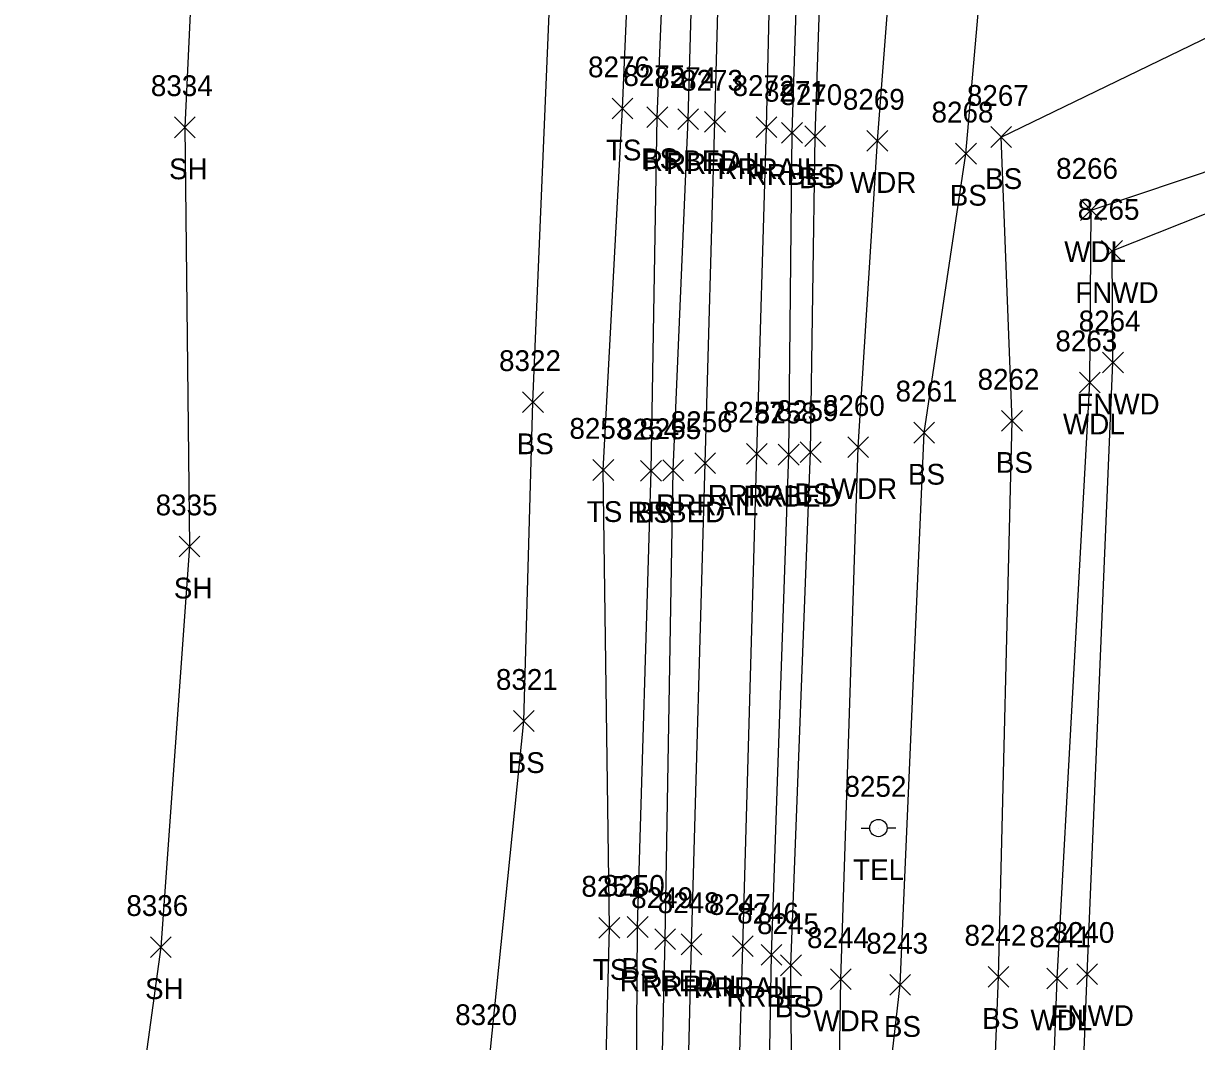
# Model space of a CAD drawing. Extents: x 1769141 to 1770911, y 735471 to 741449.
# Drawn here: x 1770212 to 1770324.8, y 737042.8 to 737140.8 of the extents above; entities that cross this region are included whole.
import ezdxf

# ---------------------------------------------------------------- set-up
doc = ezdxf.new("R2010")
doc.units = 0
for name, color, linetype in [('L_A', 7, 'Continuous'), ('L_I', 7, 'Continuous'), ('L_TIC', 7, 'Continuous'), ('LAWA', 7, 'Continuous'), ('LELB', 7, 'Continuous'), ('LFNC', 7, 'Continuous'), ('LSOGP', 7, 'Continuous'), ('R_A', 7, 'Continuous'), ('R_I', 7, 'Continuous'), ('R_TIC', 7, 'Continuous'), ('RR', 7, 'Continuous'), ('RRB', 7, 'Continuous'), ('U_A', 7, 'Continuous'), ('U_I', 7, 'Continuous'), ('UP', 7, 'Continuous')]:
    doc.layers.add(name, color=color, linetype=linetype)

msp = doc.modelspace()

# ---------------------------------------------------------------- linework, layer by layer
at = {"layer": 'L_TIC'}
for points in [[(1770268.57, 737131.6), (1770270.57, 737133.6)], [(1770270.57, 737131.6), (1770268.57, 737133.6)], [(1770271.92, 737130.76), (1770273.92, 737132.76)], [(1770273.92, 737130.76), (1770271.92, 737132.76)], [(1770226.47, 737129.79), (1770228.47, 737131.79)], [(1770228.47, 737129.79), (1770226.47, 737131.79)], [(1770287.1, 737128.93), (1770289.1, 737130.93)], [(1770289.1, 737128.93), (1770287.1, 737130.93)], [(1770293.09, 737128.48), (1770295.09, 737130.48)], [(1770295.09, 737128.48), (1770293.09, 737130.48)], [(1770305, 737128.85), (1770307, 737130.85)], [(1770307, 737128.85), (1770305, 737130.85)], [(1770301.61, 737127.25), (1770303.61, 737129.25)], [(1770303.61, 737127.25), (1770301.61, 737129.25)], [(1770313.64, 737121.83), (1770315.64, 737123.83)], [(1770315.64, 737121.83), (1770313.64, 737123.83)], [(1770315.66, 737117.89), (1770317.66, 737119.89)], [(1770317.66, 737117.89), (1770315.66, 737119.89)], [(1770315.75, 737107.16), (1770317.75, 737109.16)], [(1770317.75, 737107.16), (1770315.75, 737109.16)], [(1770313.52, 737105.24), (1770315.52, 737107.24)], [(1770315.52, 737105.24), (1770313.52, 737107.24)], [(1770259.96, 737103.34), (1770261.96, 737105.34)], [(1770261.96, 737103.34), (1770259.96, 737105.34)], [(1770306.04, 737101.55), (1770308.04, 737103.55)], [(1770308.04, 737101.55), (1770306.04, 737103.55)], [(1770297.58, 737100.41), (1770299.58, 737102.41)], [(1770299.58, 737100.41), (1770297.58, 737102.41)], [(1770286.67, 737098.53), (1770288.67, 737100.53)], [(1770288.67, 737098.53), (1770286.67, 737100.53)], [(1770291.25, 737099.02), (1770293.25, 737101.02)], [(1770293.25, 737099.02), (1770291.25, 737101.02)], [(1770266.73, 737096.82), (1770268.73, 737098.82)], [(1770268.73, 737096.82), (1770266.73, 737098.82)], [(1770271.32, 737096.75), (1770273.32, 737098.75)], [(1770273.32, 737096.75), (1770271.32, 737098.75)], [(1770226.93, 737089.46), (1770228.93, 737091.46)], [(1770228.93, 737089.46), (1770226.93, 737091.46)], [(1770259.09, 737072.67), (1770261.09, 737074.67)], [(1770261.09, 737072.67), (1770259.09, 737074.67)], [(1770267.31, 737052.77), (1770269.31, 737054.77)], [(1770269.31, 737052.77), (1770267.31, 737054.77)], [(1770270.03, 737052.86), (1770272.03, 737054.86)], [(1770272.03, 737052.86), (1770270.03, 737054.86)], [(1770224.16, 737050.92), (1770226.16, 737052.92)], [(1770226.16, 737050.92), (1770224.16, 737052.92)], [(1770284.78, 737049.17), (1770286.78, 737051.17)], [(1770286.78, 737049.17), (1770284.78, 737051.17)], [(1770289.58, 737047.83), (1770291.58, 737049.83)], [(1770291.58, 737047.83), (1770289.58, 737049.83)], [(1770304.73, 737048.06), (1770306.73, 737050.06)], [(1770306.73, 737048.06), (1770304.73, 737050.06)], [(1770310.39, 737047.91), (1770312.39, 737049.91)], [(1770312.39, 737047.91), (1770310.39, 737049.91)], [(1770313.27, 737048.33), (1770315.27, 737050.33)], [(1770315.27, 737048.33), (1770313.27, 737050.33)], [(1770295.28, 737047.29), (1770297.28, 737049.29)], [(1770297.28, 737047.29), (1770295.28, 737049.29)]]:
    msp.add_lwpolyline(points, dxfattribs=at)
at = {"layer": 'LAWA'}
for points in [[(1770295.56, 736765.07), (1770288.47, 736765.03), (1770285.4, 736787.87), (1770284.57, 736804.63), (1770282.38, 736833.87), (1770287.4, 736893.59), (1770286.58, 736936.63), (1770289.46, 736968.99), (1770291.49, 736986.73), (1770290, 737012.94), (1770290.58, 737048.83), (1770292.25, 737100.02), (1770294.09, 737129.48), (1770297.9, 737178.74), (1770298.45, 737224.98), (1770303.27, 737281.64), (1770303.62, 737324.77), (1770304.03, 737377.4)], [(1770295.56, 736765.07), (1770298.44, 736807.53), (1770300.94, 736833.02), (1770303.15, 736868.46), (1770304.73, 736899.95), (1770312.24, 736920.03), (1770307.96, 736948.77), (1770308.9, 736965.25), (1770306.38, 736996.36), (1770309.8, 737006.68), (1770311.39, 737048.91), (1770314.52, 737106.24), (1770314.64, 737122.83), (1770358.1, 737137.42)]]:
    msp.add_lwpolyline(points, dxfattribs=at)
at = {"layer": 'LELB'}
for points in [[(1770284.22, 736983.53), (1770286.1, 737006.52), (1770285.78, 737050.17), (1770287.67, 737099.53), (1770288.1, 737129.93), (1770289.78, 737179.54), (1770290.91, 737225.58), (1770293.69, 737274.35), (1770294.72, 737325.7), (1770295.85, 737386.33), (1770296.79, 737425.26), (1770298.1, 737467.61), (1770299.88, 737513.29), (1770300.86, 737550.57), (1770302.69, 737591.97), (1770303.34, 737644.67), (1770305.34, 737693.43), (1770307.48, 737738.89), (1770308.5, 737789.11), (1770309.29, 737836.41), (1770310.87, 737872.45)], [(1770269.27, 736974.12), (1770270.69, 737003.92), (1770271.03, 737053.86), (1770272.32, 737097.75), (1770272.92, 737131.76), (1770274.84, 737178.2), (1770275.61, 737227.83), (1770277.38, 737274.26), (1770278.99, 737326.74), (1770280.59, 737386.92), (1770281.43, 737425.53), (1770282.04, 737467.46), (1770283.44, 737512.78), (1770283.79, 737551.85), (1770285.35, 737592.82), (1770287.29, 737644.47), (1770288.42, 737691.85), (1770289.44, 737741.02), (1770289.98, 737788.31), (1770291.46, 737837.25)], [(1770249.46, 736962.04), (1770263.88, 736963.02), (1770266.91, 736974.5), (1770267.05, 737003.42), (1770268.31, 737053.77), (1770267.73, 737097.82), (1770269.57, 737132.6), (1770271.52, 737178.02), (1770272.76, 737227.71), (1770272.04, 737273.95), (1770277.42, 737326.8), (1770278.12, 737387.36), (1770277.35, 737426.21), (1770278.82, 737466.73), (1770278.22, 737491.37), (1770271.32, 737497.06), (1770272.28, 737508.08), (1770279.53, 737512.94), (1770280.12, 737551.03), (1770278.93, 737574.69)], [(1770292.28, 737013.24), (1770296.28, 737048.29), (1770298.58, 737101.41), (1770302.61, 737128.25), (1770304.78, 737153.09), (1770306.98, 737198.89), (1770310.91, 737276.4), (1770319.23, 737323.49), (1770312.01, 737369.68)], [(1770223.3, 736999.74), (1770247.32, 736993.47), (1770249.33, 736982.02), (1770256.99, 736968.47), (1770258.56, 736968.25), (1770259.68, 736979.83), (1770259.53, 737007.75), (1770256.82, 737041.42), (1770260.09, 737073.67), (1770260.96, 737104.34), (1770262.97, 737152.46), (1770265.19, 737198.57), (1770266.09, 737235.37), (1770266.57, 737271.78), (1770267.99, 737295.65), (1770265.74, 737320.11), (1770261.62, 737337.17)], [(1770304.12, 737007.29), (1770305.73, 737049.06), (1770307.04, 737102.55), (1770306, 737129.85), (1770351.63, 737151.97)]]:
    msp.add_lwpolyline(points, dxfattribs=at)
at = {"layer": 'LFNC'}
msp.add_lwpolyline([(1770310.45, 736948.6), (1770310.85, 736965.36), (1770312.27, 736998.82), (1770312.61, 737007.06), (1770314.27, 737049.33), (1770316.75, 737108.16), (1770316.66, 737118.89), (1770347.68, 737131.23)], dxfattribs=at)
at = {"layer": 'LSOGP'}
msp.add_lwpolyline([(1770232.14, 737271.5), (1770229.99, 737225.16), (1770229.81, 737180.79), (1770227.47, 737130.79), (1770227.93, 737090.46), (1770225.16, 737051.92), (1770220.96, 737021.3), (1770223.3, 736999.74), (1770222.78, 736985.92), (1770211.96, 736934.94)], dxfattribs=at)
at = {"layer": 'R_TIC'}
for points in [[(1770274.89, 737130.57), (1770276.89, 737132.57)], [(1770276.89, 737130.57), (1770274.89, 737132.57)], [(1770277.47, 737130.31), (1770279.47, 737132.31)], [(1770279.47, 737130.31), (1770277.47, 737132.31)], [(1770282.42, 737129.8), (1770284.42, 737131.8)], [(1770284.42, 737129.8), (1770282.42, 737131.8)], [(1770284.88, 737129.25), (1770286.88, 737131.25)], [(1770286.88, 737129.25), (1770284.88, 737131.25)], [(1770276.52, 737097.47), (1770278.52, 737099.47)], [(1770278.52, 737097.47), (1770276.52, 737099.47)], [(1770281.49, 737098.38), (1770283.49, 737100.38)], [(1770283.49, 737098.38), (1770281.49, 737100.38)], [(1770284.56, 737098.3), (1770286.56, 737100.3)], [(1770286.56, 737098.3), (1770284.56, 737100.3)], [(1770273.45, 737096.79), (1770275.45, 737098.79)], [(1770275.45, 737096.79), (1770273.45, 737098.79)], [(1770272.67, 737051.68), (1770274.67, 737053.68)], [(1770274.67, 737051.68), (1770272.67, 737053.68)], [(1770275.22, 737051.19), (1770277.22, 737053.19)], [(1770277.22, 737051.19), (1770275.22, 737053.19)], [(1770280.15, 737051.02), (1770282.15, 737053.02)], [(1770282.15, 737051.02), (1770280.15, 737053.02)], [(1770282.91, 737050.19), (1770284.91, 737052.19)], [(1770284.91, 737050.19), (1770282.91, 737052.19)]]:
    msp.add_lwpolyline(points, dxfattribs=at)
at = {"layer": 'RR'}
for points in [[(1770267.4, 736722.31), (1770268.34, 736758.82), (1770269.57, 736804.44), (1770270.45, 736834.65), (1770272.42, 736909.27), (1770273.15, 736938.32), (1770274.05, 736970.76), (1770275.07, 737005.76), (1770276.22, 737052.19), (1770277.52, 737098.47), (1770278.47, 737131.31), (1770279.73, 737178.68), (1770281, 737226.57), (1770282.34, 737274.07)], [(1770272.41, 736722.1), (1770273.29, 736759.01), (1770274.62, 736804.33), (1770275.38, 736834.93), (1770277.26, 736906.22), (1770278.11, 736938.08), (1770278.9, 736969.65), (1770279.86, 737006.36), (1770281.15, 737052.02), (1770282.49, 737099.38), (1770283.42, 737130.8), (1770284.55, 737178.73), (1770285.97, 737226.12), (1770287.25, 737273.96)]]:
    msp.add_lwpolyline(points, dxfattribs=at)
at = {"layer": 'RRB'}
for points in [[(1770264.61, 736722.25), (1770265.29, 736759.21), (1770266.68, 736803.74), (1770267.29, 736834.32), (1770268.85, 736909.78), (1770270.22, 736938.92), (1770271.46, 736972.05), (1770272.55, 737004.83), (1770273.67, 737052.68), (1770274.45, 737097.79), (1770275.89, 737131.57), (1770277.22, 737178.3), (1770278.92, 737227.05), (1770280.11, 737274.21)], [(1770275.05, 736722.18), (1770278.17, 736759.08), (1770279.42, 736805.27), (1770278.55, 736834.64), (1770280.9, 736900.53), (1770282.38, 736937.77), (1770283.59, 736969.2), (1770283.11, 737006.43), (1770283.91, 737051.19), (1770285.56, 737099.3), (1770285.88, 737130.25), (1770287.46, 737178.49), (1770288.76, 737226.01), (1770290.63, 737273.86)]]:
    msp.add_lwpolyline(points, dxfattribs=at)
at = {"layer": 'UP'}
for p, q in [((1770292.54, 737063.37), (1770293.36, 737063.37)), ((1770294.19, 737063.38), (1770294.19, 737063.38)), ((1770295.86, 737063.38), (1770295.03, 737063.38)), ((1770295.03, 737063.38), (1770295.03, 737063.38)), ((1770295.86, 737063.38), (1770295.86, 737063.38))]:
    msp.add_line(p, q, dxfattribs=at)
msp.add_circle((1770294.19, 737063.38), 0.833, dxfattribs=at)

# ---------------------------------------------------------------- texts
at = {"layer": 'L_A'}
for s, p in [('TS', (1770267.98, 737127.6)), ('BS', (1770271.36, 737126.76)), ('SH', (1770225.96, 737125.79)), ('BS', (1770286.54, 737124.93)), ('WDR', (1770291.45, 737124.48)), ('BS', (1770304.45, 737124.85)), ('BS', (1770301.05, 737123.25)), ('WDL', (1770312.06, 737117.83)), ('FNWD', (1770313.12, 737113.89)), ('FNWD', (1770313.22, 737103.16)), ('WDL', (1770311.94, 737101.24)), ('BS', (1770259.4, 737099.34)), ('BS', (1770305.48, 737097.55)), ('BS', (1770297.03, 737096.41)), ('BS', (1770286.11, 737094.53)), ('WDR', (1770289.61, 737095.02)), ('TS', (1770266.14, 737092.82)), ('BS', (1770270.76, 737092.75)), ('SH', (1770226.42, 737085.46)), ('BS', (1770258.53, 737068.67)), ('BS', (1770269.48, 737048.86)), ('TS', (1770266.72, 737048.77)), ('SH', (1770223.65, 737046.92)), ('BS', (1770284.22, 737045.17)), ('WDR', (1770287.94, 737043.83)), ('BS', (1770294.72, 737043.29)), ('BS', (1770304.17, 737044.06)), ('WDL', (1770308.81, 737043.91)), ('FNWD', (1770310.74, 737044.33))]:
    msp.add_text(s, height=2, dxfattribs=at).set_placement(p)
at = {"layer": 'L_I'}
for s, p in [('8276', (1770266.26, 737135.6)), ('8275', (1770269.66, 737134.76)), ('8334', (1770224.21, 737133.79)), ('8270', (1770284.76, 737132.93)), ('8269', (1770290.77, 737132.48)), ('8267', (1770302.7, 737132.85)), ('8268', (1770299.3, 737131.25)), ('8266', (1770311.28, 737125.83)), ('8265', (1770313.35, 737121.89)), ('8264', (1770313.45, 737111.16)), ('8263', (1770311.21, 737109.24)), ('8322', (1770257.7, 737107.34)), ('8262', (1770303.73, 737105.55)), ('8261', (1770295.84, 737104.41)), ('8260', (1770288.85, 737103.02)), ('8259', (1770284.4, 737102.53)), ('8253', (1770264.47, 737100.82)), ('8254', (1770269.06, 737100.75)), ('8335', (1770224.67, 737093.46)), ('8321', (1770257.4, 737076.67)), ('8251', (1770265.62, 737056.77)), ('8250', (1770267.69, 737056.86)), ('8336', (1770221.85, 737054.92)), ('8245', (1770282.52, 737053.17)), ('8240', (1770310.93, 737052.33)), ('8244', (1770287.32, 737051.83)), ('8243', (1770293.02, 737051.29)), ('8242', (1770302.47, 737052.06)), ('8241', (1770308.7, 737051.91)), ('8320', (1770253.48, 737044.42))]:
    msp.add_text(s, height=2, dxfattribs=at).set_placement(p)
at = {"layer": 'R_A'}
for s, p in [('RRBED', (1770271.54, 737126.57)), ('RRRAIL', (1770273.76, 737126.31)), ('RRRAIL', (1770278.71, 737125.8)), ('RRBED', (1770281.52, 737125.25)), ('RRRAIL', (1770277.78, 737094.38)), ('RRBED', (1770281.2, 737094.3)), ('RRRAIL', (1770272.81, 737093.47)), ('RRBED', (1770270.09, 737092.79)), ('RRBED', (1770269.32, 737047.68)), ('RRRAIL', (1770271.51, 737047.19)), ('RRRAIL', (1770276.44, 737047.02)), ('RRBED', (1770279.56, 737046.19))]:
    msp.add_text(s, height=2, dxfattribs=at).set_placement(p)
at = {"layer": 'R_I'}
for s, p in [('8274', (1770272.63, 737134.57)), ('8273', (1770275.21, 737134.31)), ('8272', (1770280.16, 737133.8)), ('8271', (1770283.18, 737133.25)), ('8257', (1770279.23, 737102.38)), ('8258', (1770282.3, 737102.3)), ('8255', (1770271.19, 737100.79)), ('8256', (1770274.21, 737101.47)), ('8249', (1770270.41, 737055.68)), ('8248', (1770272.96, 737055.19)), ('8247', (1770277.89, 737055.02)), ('8246', (1770280.6, 737054.19))]:
    msp.add_text(s, height=2, dxfattribs=at).set_placement(p)
at = {"layer": 'U_A'}
msp.add_text('TEL', height=2, dxfattribs=at).set_placement((1770291.75, 737058.38))
at = {"layer": 'U_I'}
msp.add_text('8252', height=2, dxfattribs=at).set_placement((1770290.93, 737066.38))

doc.saveas('drawing.dxf')
